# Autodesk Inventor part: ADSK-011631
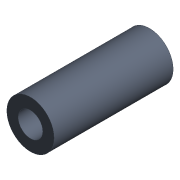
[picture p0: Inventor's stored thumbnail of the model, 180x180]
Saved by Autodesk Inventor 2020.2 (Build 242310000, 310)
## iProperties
Created: 2000-02
Part Number: ADSK-011631
Material: Pearson Nylatron
Document SubType Name: Modeling
Description: TUBERD,RN,AX,10,05,025,ROLLER,SIDE GUIDE ASSY
Designer: sspink
Density: 1.13867 g/cm^3
Appearance: Nylatron
Mass: 25.6917 g
Surface Area: 82.3726 cm^2
Volume: 22.5629 cm^3
Control State: 0
Checked Out: False
Master: False
Shininess: 10.0
Length Units: 11269
Angle Units: 11279
Time Units: 11290
Mass Units: 11283
Length Display Precision: 3
Angle Display Precision: 2
Compacted: True
Cutlength: 2.5
Material Desc: ROUND,NYLATRON,1.0000
Material_Number: A088707
Dimensions: 25x63x25 mm
Mass: 0,026 kg
VLT_Material: Pearson Nylatron
Density: 1.13867
Volumn: 23.621339414680698
Area: 84.2376442423462
PropertySet Name: Model Information
Author: sspink
Revision Number: -
Title: TUBERD,RN,AX,10,05,025,ROLLER,SIDE GUIDE ASSY
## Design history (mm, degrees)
node "Solide1"
  node "Extrusion1" dims "d2" = 63, "d3" = 0
sketch "Sketch1"
  geometry: C1 r 12.5 at (0, 0); C2 r 6.5 at (0, 0); 1 further point
  constraints: 2 centre point, 2 coincident
  dimensions: "d0" = 25 diameter of C1; "d1" = 13 diameter of C2
node "Corps solides"
node "Corps surfaciques"
